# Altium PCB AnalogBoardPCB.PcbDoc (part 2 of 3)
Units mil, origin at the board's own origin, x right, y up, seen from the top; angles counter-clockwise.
Board outline 5875 x 2550 mil, 4 copper layers (Top Layer, GND, VCC, Bottom Layer); 569 components, 22 nets, 1336 pads, 360 vias.
Unrouted connection lines stored in the file: 31.
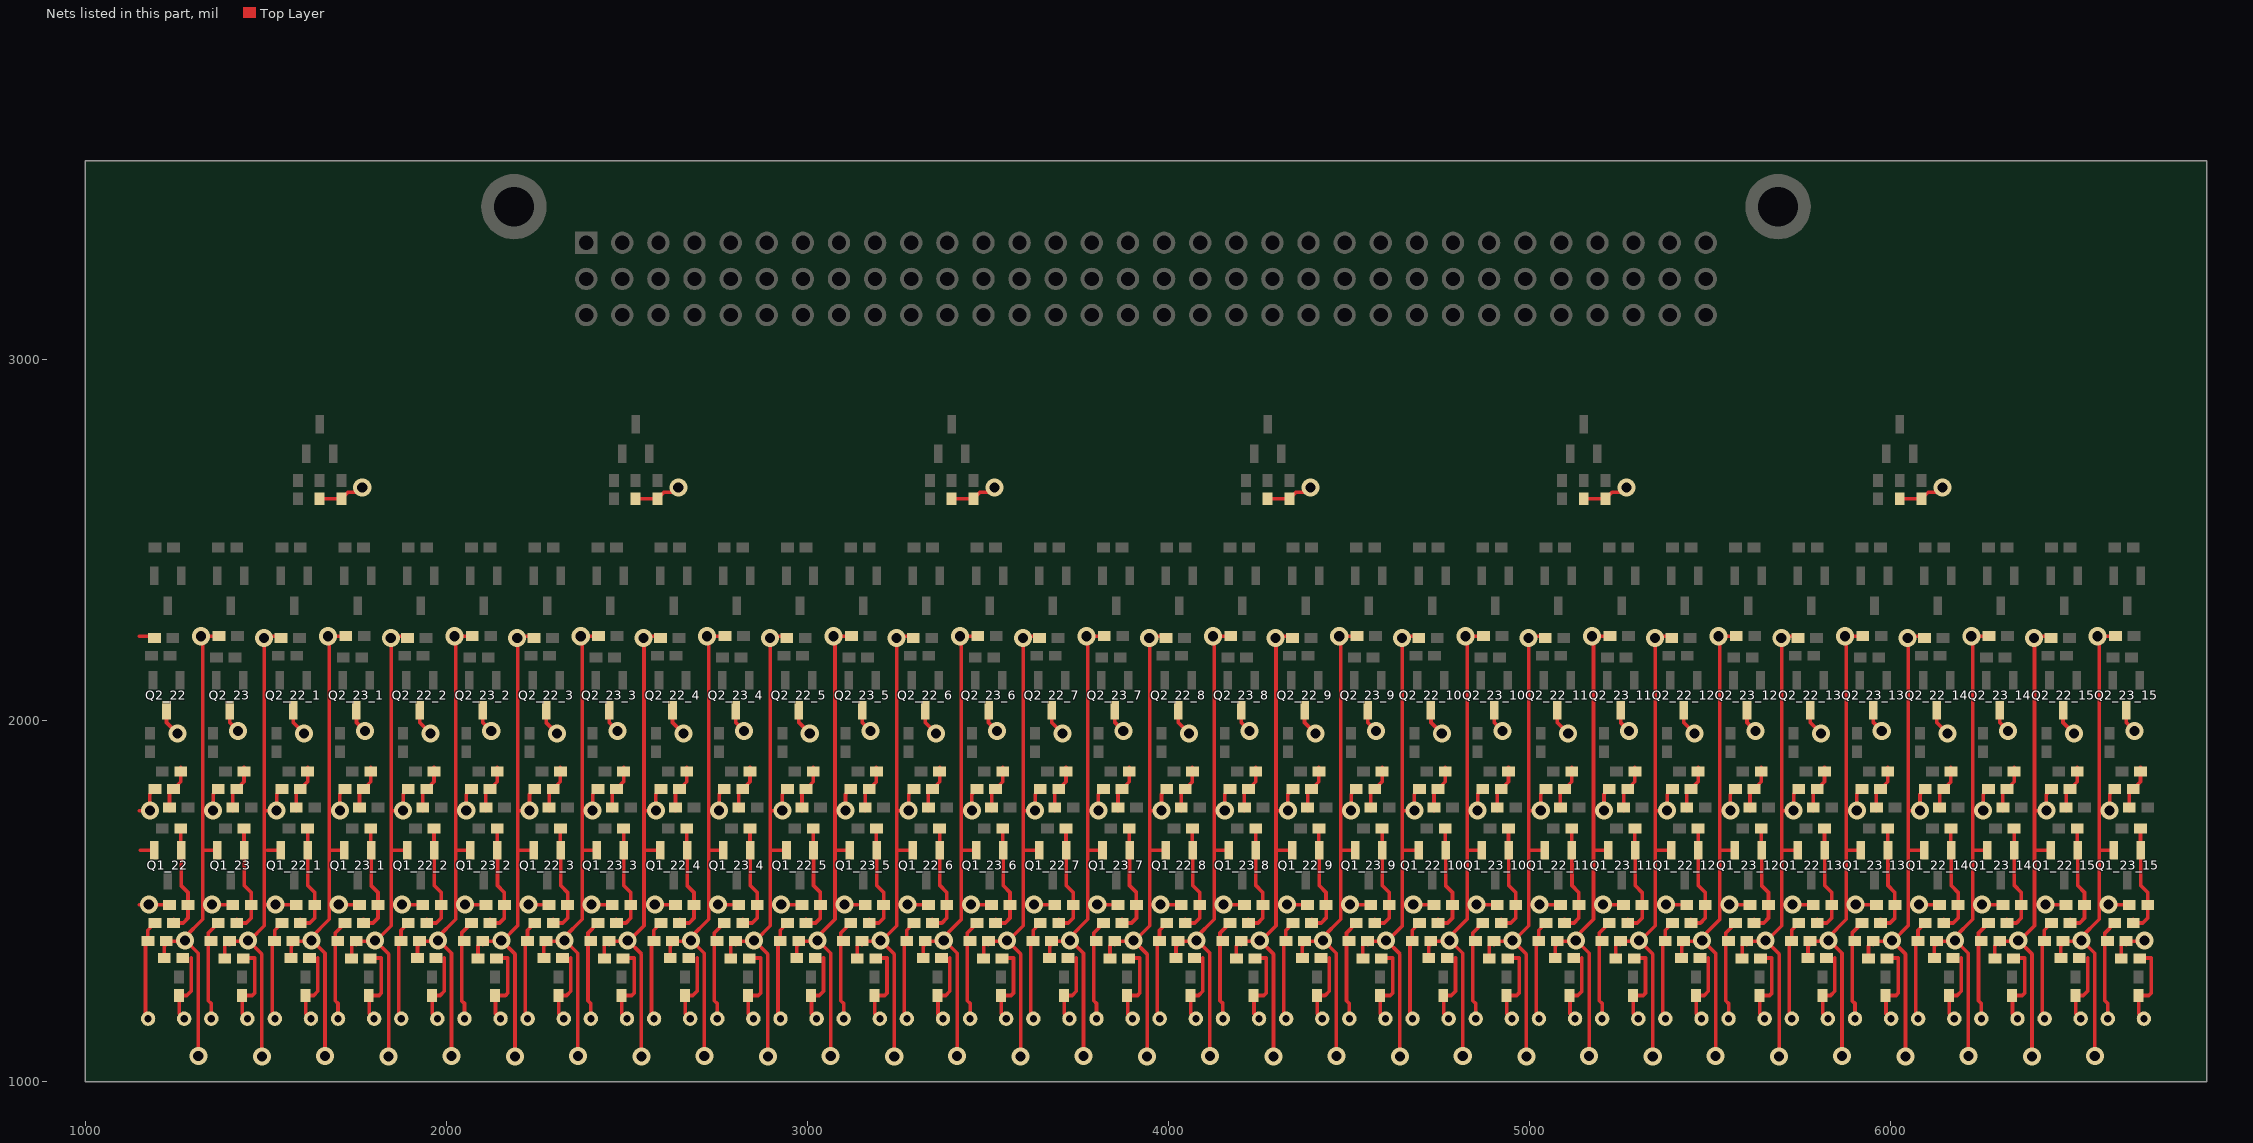
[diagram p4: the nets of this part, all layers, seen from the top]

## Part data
C1_22 C1_22_1 C1_22_2 C1_22_3 C1_22_4 C1_22_5 C1_22_6 C1_22_7 C1_22_8 C1_22_9 C1_22_10 C1_22_11 C1_22_12 C1_22_13 C1_22_14 C1_22_15 C1_23 C1_23_1 C1_23_2 C1_23_3 C1_23_4 C1_23_5 C1_23_6 C1_23_7 C1_23_8 C1_23_9 C1_23_10 C1_23_11 C1_23_12 C1_23_13 C1_23_14 C1_23_15 C2_22 C2_22_1 C2_22_2 C2_22_3 C2_22_4 C2_22_5 C2_22_6 C2_22_7 C2_22_8 C2_22_9 C2_22_10 C2_22_11 C2_22_12 C2_22_13 C2_22_14 C2_22_15 C2_23 C2_23_1 C2_23_2 C2_23_3 C2_23_4 C2_23_5 C2_23_6 C2_23_7 C2_23_8 C2_23_9 C2_23_10 C2_23_11 C2_23_12 C2_23_13 C2_23_14 C2_23_15 C3_22 C3_22_1 C3_22_2 C3_22_3 C3_22_4 C3_22_5 C3_22_6 C3_22_7 C3_22_8 C3_22_9 C3_22_10 C3_22_11 C3_22_12 C3_22_13 C3_22_14 C3_22_15 C3_23 C3_23_1 C3_23_2 C3_23_3 C3_23_4 C3_23_5 C3_23_6 C3_23_7 C3_23_8 C3_23_9 C3_23_10 C3_23_11 C3_23_12 C3_23_13 C3_23_14 C3_23_15 C4_22 C4_22_1 C4_22_2 C4_22_3 C4_22_4 C4_22_5 C4_22_6 C4_22_7 C4_22_8 C4_22_9 C4_22_10 C4_22_11 C4_22_12 C4_22_13 C4_22_14 C4_22_15 C4_23 C4_23_1 C4_23_2 C4_23_3 C4_23_4 C4_23_5 C4_23_6 C4_23_7 C4_23_8 C4_23_9 C4_23_10 C4_23_11 C4_23_12 C4_23_13 C4_23_14 C4_23_15: "Capacitor"
D1_22 D1_22_1 D1_22_2 D1_22_3 D1_22_4 D1_22_5 D1_22_6 D1_22_7 D1_22_8 D1_22_9 D1_22_10 D1_22_11 D1_22_12 D1_22_13 D1_22_14 D1_22_15 D1_23 D1_23_1 D1_23_2 D1_23_3 D1_23_4 D1_23_5 D1_23_6 D1_23_7 D1_23_8 D1_23_9 D1_23_10 D1_23_11 D1_23_12 D1_23_13 D1_23_14 D1_23_15: library part "Photo Sen", "Photosensitive Diode"
Q1_22 Q1_22_1 Q1_22_2 Q1_22_3 Q1_22_4 Q1_22_5 Q1_22_6 Q1_22_7 Q1_22_8 Q1_22_9 Q1_22_10 Q1_22_11 Q1_22_12 Q1_22_13 Q1_22_14 Q1_22_15 Q1_23 Q1_23_1 Q1_23_2 Q1_23_3 Q1_23_4 Q1_23_5 Q1_23_6 Q1_23_7 Q1_23_8 Q1_23_9 Q1_23_10 Q1_23_11 Q1_23_12 Q1_23_13 Q1_23_14 Q1_23_15 Q2_22 Q2_22_1 Q2_22_2 Q2_22_3 Q2_22_4 Q2_22_5 Q2_22_6 Q2_22_7 Q2_22_8 Q2_22_9 Q2_22_10 Q2_22_11 Q2_22_12 Q2_22_13 Q2_22_14 Q2_22_15 Q2_23 Q2_23_1 Q2_23_2 Q2_23_3 Q2_23_4 Q2_23_5 Q2_23_6 Q2_23_7 Q2_23_8 Q2_23_9 Q2_23_10 Q2_23_11 Q2_23_12 Q2_23_13 Q2_23_14 Q2_23_15: library part BFS19, "NPN Medium Frequency Transistor"
Q1_32 Q1_32_1 Q1_32_2 Q1_32_3 Q1_32_4 Q1_32_5: "NPN 3 GHz Wideband Transistor"
Q3_22 Q3_22_1 Q3_22_2 Q3_22_3 Q3_22_4 Q3_22_5 Q3_22_6 Q3_22_7 Q3_22_8 Q3_22_9 Q3_22_10 Q3_22_11 Q3_22_12 Q3_22_13 Q3_22_14 Q3_22_15 Q3_23 Q3_23_1 Q3_23_2 Q3_23_3 Q3_23_4 Q3_23_5 Q3_23_6 Q3_23_7 Q3_23_8 Q3_23_9 Q3_23_10 Q3_23_11 Q3_23_12 Q3_23_13 Q3_23_14 Q3_23_15: "PNP 5 GHz Wideband Transistor"
R1_22 R1_22_1 R1_22_2 R1_22_3 R1_22_4 R1_22_5 R1_22_6 R1_22_7 R1_22_8 R1_22_9 R1_22_10 R1_22_11 R1_22_12 R1_22_13 R1_22_14 R1_22_15 R1_23 R1_23_1 R1_23_2 R1_23_3 R1_23_4 R1_23_5 R1_23_6 R1_23_7 R1_23_8 R1_23_9 R1_23_10 R1_23_11 R1_23_12 R1_23_13 R1_23_14 R1_23_15 R1_32 R1_32_1 R1_32_2 R1_32_3 R1_32_4 R1_32_5 R2_22 R2_22_1 R2_22_2 R2_22_3 R2_22_4 R2_22_5 R2_22_6 R2_22_7 R2_22_8 R2_22_9 R2_22_10 R2_22_11 R2_22_12 R2_22_13 R2_22_14 R2_22_15 R2_23 R2_23_1 R2_23_2 R2_23_3 R2_23_4 R2_23_5 R2_23_6 R2_23_7 R2_23_8 R2_23_9 R2_23_10 R2_23_11 R2_23_12 R2_23_13 R2_23_14 R2_23_15 R2_32 R2_32_1 R2_32_2 R2_32_3 R2_32_4 R2_32_5 R3_22 R3_22_1 R3_22_2 R3_22_3 R3_22_4 R3_22_5 R3_22_6 R3_22_7 R3_22_8 R3_22_9 R3_22_10 R3_22_11 R3_22_12 R3_22_13 R3_22_14 R3_22_15 R3_23 R3_23_1 R3_23_2 R3_23_3 R3_23_4 R3_23_5 R3_23_6 R3_23_7 R3_23_8 R3_23_9 R3_23_10 R3_23_11 R3_23_12 R3_23_13 R3_23_14 R3_23_15 R3_32 R3_32_1 R3_32_2 R3_32_3 R3_32_4 R3_32_5 R4_22 R4_22_1 R4_22_2 R4_22_3 R4_22_4 R4_22_5 R4_22_6 R4_22_7 R4_22_8 R4_22_9 R4_22_10 R4_22_11 R4_22_12 R4_22_13 R4_22_14 R4_22_15 R4_23 R4_23_1 R4_23_2 R4_23_3 R4_23_4 R4_23_5 R4_23_6 R4_23_7 R4_23_8 R4_23_9 R4_23_10 R4_23_11 R4_23_12 R4_23_13 R4_23_14 R4_23_15 R5_22 R5_22_1 R5_22_2 R5_22_3 R5_22_4 R5_22_5 R5_22_6 R5_22_7 R5_22_8 R5_22_9 R5_22_10 R5_22_11 R5_22_12 R5_22_13 R5_22_14 R5_22_15 R5_23 R5_23_1 R5_23_2 R5_23_3 R5_23_4 R5_23_5 R5_23_6 R5_23_7 R5_23_8 R5_23_9 R5_23_10 R5_23_11 R5_23_12 R5_23_13 R5_23_14 R5_23_15 R6_22 R6_22_1 R6_22_2 R6_22_3 R6_22_4 R6_22_5 R6_22_6 R6_22_7 R6_22_8 R6_22_9 R6_22_10 R6_22_11 R6_22_12 R6_22_13 R6_22_14 R6_22_15 R6_23 R6_23_1 R6_23_2 R6_23_3 R6_23_4 R6_23_5 R6_23_6 R6_23_7 R6_23_8 R6_23_9 R6_23_10 R6_23_11 R6_23_12 R6_23_13 R6_23_14 R6_23_15 R7_22 R7_22_1 R7_22_2 R7_22_3 R7_22_4 R7_22_5 R7_22_6 R7_22_7 R7_22_8 R7_22_9 R7_22_10 R7_22_11 R7_22_12 R7_22_13 R7_22_14 R7_22_15 R7_23 R7_23_1 R7_23_2 R7_23_3 R7_23_4 R7_23_5 R7_23_6 R7_23_7 R7_23_8 R7_23_9 R7_23_10 R7_23_11 R7_23_12 R7_23_13 R7_23_14 R7_23_15 R8_22 R8_22_1 R8_22_2 R8_22_3 R8_22_4 R8_22_5 R8_22_6 R8_22_7 R8_22_8 R8_22_9 R8_22_10 R8_22_11 R8_22_12 R8_22_13 R8_22_14 R8_22_15 R8_23 R8_23_1 R8_23_2 R8_23_3 R8_23_4 R8_23_5 R8_23_6 R8_23_7 R8_23_8 R8_23_9 R8_23_10 R8_23_11 R8_23_12 R8_23_13 R8_23_14 R8_23_15 R9_22 R9_22_1 R9_22_2 R9_22_3 R9_22_4 R9_22_5 R9_22_6 R9_22_7 R9_22_8 R9_22_9 R9_22_10 R9_22_11 R9_22_12 R9_22_13 R9_22_14 R9_22_15 R9_23 R9_23_1 R9_23_2 R9_23_3 R9_23_4 R9_23_5 R9_23_6 R9_23_7 R9_23_8 R9_23_9 R9_23_10 R9_23_11 R9_23_12 R9_23_13 R9_23_14 R9_23_15: "Resistor"

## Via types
v1: diameter 50, hole 28, Top Layer to Bottom Layer, 327 vias
v2: diameter 50, hole 28, Top Layer to Bottom Layer, tented top, 31 vias
v3: diameter 50, hole 28, Top Layer to Bottom Layer, tented both sides, 2 vias

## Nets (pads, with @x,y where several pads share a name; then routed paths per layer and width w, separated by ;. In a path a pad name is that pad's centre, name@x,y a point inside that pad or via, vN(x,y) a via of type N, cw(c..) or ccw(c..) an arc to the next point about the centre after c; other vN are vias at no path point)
GND: C1_22.2 C1_22_1.2 C1_22_2.2 C1_22_3.2 C1_22_4.2 C1_22_5.2 C1_22_6.2 C1_22_7.2 C1_22_8.2 C1_22_9.2 C1_22_10.2 C1_22_11.2 C1_22_12.2 C1_22_13.2 C1_22_14.2 C1_22_15.2 C1_23.2 C1_23_1.2 C1_23_2.2 C1_23_3.2 C1_23_4.2 C1_23_5.2 C1_23_6.2 C1_23_7.2 C1_23_8.2 C1_23_9.2 C1_23_10.2 C1_23_11.2 C1_23_12.2 C1_23_13.2 C1_23_14.2 C1_23_15.2 C2_22.1 C2_22_1.1 C2_22_2.1 C2_22_3.1 C2_22_4.1 C2_22_5.1 C2_22_6.1 C2_22_7.1 C2_22_8.1 C2_22_9.1 C2_22_10.1 C2_22_11.1 C2_22_12.1 C2_22_13.1 C2_22_14.1 C2_22_15.1 C2_23.1 C2_23_1.1 C2_23_2.1 C2_23_3.1 C2_23_4.1 C2_23_5.1 C2_23_6.1 C2_23_7.1 C2_23_8.1 C2_23_9.1 C2_23_10.1 C2_23_11.1 C2_23_12.1 C2_23_13.1 C2_23_14.1 C2_23_15.1 Q1_22.2 Q1_22_1.2 Q1_22_2.2 Q1_22_3.2 Q1_22_4.2 Q1_22_5.2 Q1_22_6.2 Q1_22_7.2 Q1_22_8.2 Q1_22_9.2 Q1_22_10.2 Q1_22_11.2 Q1_22_12.2 Q1_22_13.2 Q1_22_14.2 Q1_22_15.2 Q1_23.2 Q1_23_1.2 Q1_23_2.2 Q1_23_3.2 Q1_23_4.2 Q1_23_5.2 Q1_23_6.2 Q1_23_7.2 Q1_23_8.2 Q1_23_9.2 Q1_23_10.2 Q1_23_11.2 Q1_23_12.2 Q1_23_13.2 Q1_23_14.2 Q1_23_15.2 Q2_22.3 Q2_22_1.3 Q2_22_2.3 Q2_22_3.3 Q2_22_4.3 Q2_22_5.3 Q2_22_6.3 Q2_22_7.3 Q2_22_8.3 Q2_22_9.3 Q2_22_10.3 Q2_22_11.3 Q2_22_12.3 Q2_22_13.3 Q2_22_14.3 Q2_22_15.3 Q2_23.3 Q2_23_1.3 Q2_23_2.3 Q2_23_3.3 Q2_23_4.3 Q2_23_5.3 Q2_23_6.3 Q2_23_7.3 Q2_23_8.3 Q2_23_9.3 Q2_23_10.3 Q2_23_11.3 Q2_23_12.3 Q2_23_13.3 Q2_23_14.3 Q2_23_15.3 R2_32.1 R2_32_1.1 R2_32_2.1 R2_32_3.1 R2_32_4.1 R2_32_5.1 R3_32.1 R3_32_1.1 R3_32_2.1 R3_32_3.1 R3_32_4.1 R3_32_5.1 R6_22.1 R6_22_1.1 R6_22_2.1 R6_22_3.1 R6_22_4.1 R6_22_5.1 R6_22_6.1 R6_22_7.1 R6_22_8.1 R6_22_9.1 R6_22_10.1 R6_22_11.1 R6_22_12.1 R6_22_13.1 R6_22_14.1 R6_22_15.1 R6_23.1 R6_23_1.1 R6_23_2.1 R6_23_3.1 R6_23_4.1 R6_23_5.1 R6_23_6.1 R6_23_7.1 R6_23_8.1 R6_23_9.1 R6_23_10.1 R6_23_11.1 R6_23_12.1 R6_23_13.1 R6_23_14.1 R6_23_15.1 R7_22.1 R7_22_1.1 R7_22_2.1 R7_22_3.1 R7_22_4.1 R7_22_5.1 R7_22_6.1 R7_22_7.1 R7_22_8.1 R7_22_9.1 R7_22_10.1 R7_22_11.1 R7_22_12.1 R7_22_13.1 R7_22_14.1 R7_22_15.1 R7_23.1 R7_23_1.1 R7_23_2.1 R7_23_3.1 R7_23_4.1 R7_23_5.1 R7_23_6.1 R7_23_7.1 R7_23_8.1 R7_23_9.1 R7_23_10.1 R7_23_11.1 R7_23_12.1 R7_23_13.1 R7_23_14.1 R7_23_15.1 R8_22.1 R8_22_1.1 R8_22_2.1 R8_22_3.1 R8_22_4.1 R8_22_5.1 R8_22_6.1 R8_22_7.1 R8_22_8.1 R8_22_9.1 R8_22_10.1 R8_22_11.1 R8_22_12.1 R8_22_13.1 R8_22_14.1 R8_22_15.1 R8_23.1 R8_23_1.1 R8_23_2.1 R8_23_3.1 R8_23_4.1 R8_23_5.1 R8_23_6.1 R8_23_7.1 R8_23_8.1 R8_23_9.1 R8_23_10.1 R8_23_11.1 R8_23_12.1 R8_23_13.1 R8_23_14.1 R8_23_15.1 | length 51418.7
  Top Layer w10: 1150.5,1490 1213.91,1490 ; 1150.5,1750 v1(1179.5,1750) 1179.5,1795.59 C2_22.1@1193.91,1810 ; 1150.5,2233 R7_22.1@1178.91,2233 ; 1153.16,1640.34 Q1_22.2@1191.1,1640.34 ; C1_22.2@1219.5,1342 1219.5,1383.41 R6_22.1@1225.09,1389 ; R6_22.1@1225.09,1379.59 R6_22.1@1225.09,1389 ; Q2_22.3@1225.5,2028.66 1225.5,1994 v1(1255.5,1964) ; v1@1274.5,1389 R6_22.1@1225.09,1389 ; v2(1313.5,1071) 1313.5,1355 1276.5,1392 1276.5,1400 1325.5,1449 1325.5,2233 R7_23.1@1374.91,2233 ; 1325.5,1490 1388.91,1490 ; 1325.5,1750 v1(1354.5,1750) 1354.5,1795.59 C2_23.1@1368.91,1810 ; 1328.16,1640.34 Q1_23.2@1366.1,1640.34 ; C1_23.2@1386.91,1341 1386.91,1375.82 R6_23.1@1400.09,1389 ; R6_23.1@1400.09,1379.59 R6_23.1@1400.09,1389 ; Q2_23.3@1400.5,2028.66 1400.5,1994 v1@1430.5,1964 ; v1@1449.5,1389 R6_23.1@1400.09,1389 ; v2(1489.5,1069) 1489.5,1353 v1(1451.5,1391) 1456.5,1391 1496.5,1431 v1@1496.5,2228 ; 1501.5,1490 1564.91,1490 ; 1501.5,1750 v1(1530.5,1750) 1530.5,1795.59 C2_22_1.1@1544.91,1810 ; v1@1501.5,2233 R7_22_1.1@1529.91,2233 ; 1504.16,1640.34 Q1_22_1.2@1542.1,1640.34 ; C1_22_1.2@1570.5,1342 1570.5,1383.41 R6_22_1.1@1576.09,1389 ; R6_22_1.1@1576.09,1379.59 R6_22_1.1@1576.09,1389 ; Q2_22_1.3@1576.5,2028.66 1576.5,1994 v1(1606.5,1964) ; v1@1625.5,1389 R6_22_1.1@1576.09,1389 ; R2_32.1@1649.5,2613.41 R3_32.1@1709.5,2613.41 1727.96,2631.87 1754.37,2631.87 v1(1767.5,2645) ; v2(1664.5,1071) 1664.5,1355 1627.5,1392 1627.5,1400 1676.5,1449 1676.5,2233 R7_23_1.1@1725.91,2233 ; 1676.5,1490 1739.91,1490 ; 1676.5,1750 v1(1705.5,1750) 1705.5,1795.59 C2_23_1.1@1719.91,1810 ; 1679.16,1640.34 Q1_23_1.2@1717.1,1640.34 ; C1_23_1.2@1737.91,1341 1737.91,1375.82 R6_23_1.1@1751.09,1389 ; R6_23_1.1@1751.09,1379.59 R6_23_1.1@1751.09,1389 ; Q2_23_1.3@1751.5,2028.66 1751.5,1994 v1@1781.5,1964 ; v1@1800.5,1389 R6_23_1.1@1751.09,1389 ; v2(1840.5,1069) 1840.5,1353 v1(1802.5,1391) 1807.5,1391 1847.5,1431 v1@1847.5,2228 ; 1851.5,1490 1914.91,1490 ; 1851.5,1750 v1(1880.5,1750) 1880.5,1795.59 C2_22_2.1@1894.91,1810 ; v1@1851.5,2233 R7_22_2.1@1879.91,2233 ; 1854.16,1640.34 Q1_22_2.2@1892.1,1640.34 ; C1_22_2.2@1920.5,1342 1920.5,1383.41 R6_22_2.1@1926.09,1389 ; R6_22_2.1@1926.09,1379.59 R6_22_2.1@1926.09,1389 ; Q2_22_2.3@1926.5,2028.66 1926.5,1994 v1(1956.5,1964) ; v1@1975.5,1389 R6_22_2.1@1926.09,1389 ; v2(2014.5,1071) 2014.5,1355 1977.5,1392 1977.5,1400 2026.5,1449 2026.5,2233 R7_23_2.1@2075.91,2233 ; 2026.5,1490 2089.91,1490 ; 2026.5,1750 v1(2055.5,1750) 2055.5,1795.59 C2_23_2.1@2069.91,1810 ; 2029.16,1640.34 Q1_23_2.2@2067.1,1640.34 ; C1_23_2.2@2087.91,1341 2087.91,1375.82 R6_23_2.1@2101.09,1389 ; R6_23_2.1@2101.09,1379.59 R6_23_2.1@2101.09,1389 ; Q2_23_2.3@2101.5,2028.66 2101.5,1994 v1@2131.5,1964 ; v1@2150.5,1389 R6_23_2.1@2101.09,1389 ; v2(2190.5,1069) 2190.5,1353 v1(2152.5,1391) 2157.5,1391 2197.5,1431 v1@2197.5,2228 ; 2201.5,1490 2264.91,1490 ; 2201.5,1750 v1(2230.5,1750) 2230.5,1795.59 C2_22_3.1@2244.91,1810 ; v1@2201.5,2233 R7_22_3.1@2229.91,2233 ; 2204.16,1640.34 Q1_22_3.2@2242.1,1640.34 ; C1_22_3.2@2270.5,1342 2270.5,1383.41 R6_22_3.1@2276.09,1389 ; R6_22_3.1@2276.09,1379.59 R6_22_3.1@2276.09,1389 ; Q2_22_3.3@2276.5,2028.66 2276.5,1994 v1(2306.5,1964) ; v1@2325.5,1389 R6_22_3.1@2276.09,1389 ; v2(2364.5,1071) 2364.5,1355 2327.5,1392 2327.5,1400 2376.5,1449 2376.5,2233 R7_23_3.1@2425.91,2233 ; 2376.5,1490 2439.91,1490 ; 2376.5,1750 v1(2405.5,1750) 2405.5,1795.59 C2_23_3.1@2419.91,1810 ; 2379.16,1640.34 Q1_23_3.2@2417.1,1640.34 ; C1_23_3.2@2437.91,1341 2437.91,1375.82 R6_23_3.1@2451.09,1389 ; R6_23_3.1@2451.09,1379.59 R6_23_3.1@2451.09,1389 ; Q2_23_3.3@2451.5,2028.66 2451.5,1994 v1@2481.5,1964 ; v1@2500.5,1389 R6_23_3.1@2451.09,1389 ; R2_32_1.1@2524.5,2613.41 R3_32_1.1@2584.5,2613.41 2602.96,2631.87 2629.37,2631.87 v1(2642.5,2645) ; v2(2540.5,1069) 2540.5,1353 v1(2502.5,1391) 2507.5,1391 2547.5,1431 v1@2547.5,2228 ; 2551.5,1490 2614.91,1490 ; 2551.5,1750 v1(2580.5,1750) 2580.5,1795.59 C2_22_4.1@2594.91,1810 ; v1@2551.5,2233 R7_22_4.1@2579.91,2233 ; 2554.16,1640.34 Q1_22_4.2@2592.1,1640.34 ; C1_22_4.2@2620.5,1342 2620.5,1383.41 R6_22_4.1@2626.09,1389 ; R6_22_4.1@2626.09,1379.59 R6_22_4.1@2626.09,1389 ; Q2_22_4.3@2626.5,2028.66 2626.5,1994 v1(2656.5,1964) ; v1@2675.5,1389 R6_22_4.1@2626.09,1389 ; v2(2714.5,1071) 2714.5,1355 2677.5,1392 2677.5,1400 2726.5,1449 2726.5,2233 R7_23_4.1@2775.91,2233 ; 2726.5,1490 2789.91,1490 ; 2726.5,1750 v1(2755.5,1750) 2755.5,1795.59 C2_23_4.1@2769.91,1810 ; 2729.16,1640.34 Q1_23_4.2@2767.1,1640.34 ; C1_23_4.2@2787.91,1341 2787.91,1375.82 R6_23_4.1@2801.09,1389 ; R6_23_4.1@2801.09,1379.59 R6_23_4.1@2801.09,1389 ; Q2_23_4.3@2801.5,2028.66 2801.5,1994 v1@2831.5,1964 ; v1@2850.5,1389 R6_23_4.1@2801.09,1389 ; v2(2890.5,1069) 2890.5,1353 v1(2852.5,1391) 2857.5,1391 2897.5,1431 v1@2897.5,2228 ; 2901.5,1490 2964.91,1490 ; 2901.5,1750 v1(2930.5,1750) 2930.5,1795.59 C2_22_5.1@2944.91,1810 ; v1@2901.5,2233 R7_22_5.1@2929.91,2233 ; 2904.16,1640.34 Q1_22_5.2@2942.1,1640.34 ; C1_22_5.2@2970.5,1342 2970.5,1383.41 R6_22_5.1@2976.09,1389 ; R6_22_5.1@2976.09,1379.59 R6_22_5.1@2976.09,1389 ; Q2_22_5.3@2976.5,2028.66 2976.5,1994 v1(3006.5,1964) ; v1@3025.5,1389 R6_22_5.1@2976.09,1389 ; v2(3064.5,1071) 3064.5,1355 3027.5,1392 3027.5,1400 3076.5,1449 3076.5,2233 R7_23_5.1@3125.91,2233 ; 3076.5,1490 3139.91,1490 ; 3076.5,1750 v1(3105.5,1750) 3105.5,1795.59 C2_23_5.1@3119.91,1810 ; 3079.16,1640.34 Q1_23_5.2@3117.1,1640.34 ; C1_23_5.2@3137.91,1341 3137.91,1375.82 R6_23_5.1@3151.09,1389 ; R6_23_5.1@3151.09,1379.59 R6_23_5.1@3151.09,1389 ; Q2_23_5.3@3151.5,2028.66 3151.5,1994 v1@3181.5,1964 ; v1@3200.5,1389 R6_23_5.1@3151.09,1389 ; v2(3240.5,1069) 3240.5,1353 v1(3202.5,1391) 3207.5,1391 3247.5,1431 v1@3247.5,2228 ; 3251.5,1490 3314.91,1490 ; 3251.5,1750 v1(3280.5,1750) 3280.5,1795.59 C2_22_6.1@3294.91,1810 ; v1@3251.5,2233 R7_22_6.1@3279.91,2233 ; 3254.16,1640.34 Q1_22_6.2@3292.1,1640.34 ; C1_22_6.2@3320.5,1342 3320.5,1383.41 R6_22_6.1@3326.09,1389 ; R6_22_6.1@3326.09,1379.59 R6_22_6.1@3326.09,1389 ; Q2_22_6.3@3326.5,2028.66 3326.5,1994 v1(3356.5,1964) ; v1@3375.5,1389 R6_22_6.1@3326.09,1389 ; R2_32_2.1@3399.5,2613.41 R3_32_2.1@3459.5,2613.41 3477.96,2631.87 3504.37,2631.87 v1(3517.5,2645) ; v2(3414.5,1071) 3414.5,1355 3377.5,1392 3377.5,1400 3426.5,1449 3426.5,2233 R7_23_6.1@3475.91,2233 ; 3426.5,1490 3489.91,1490 ; 3426.5,1750 v1(3455.5,1750) 3455.5,1795.59 C2_23_6.1@3469.91,1810 ; 3429.16,1640.34 Q1_23_6.2@3467.1,1640.34 ; C1_23_6.2@3487.91,1341 3487.91,1375.82 R6_23_6.1@3501.09,1389 ; R6_23_6.1@3501.09,1379.59 R6_23_6.1@3501.09,1389 ; Q2_23_6.3@3501.5,2028.66 3501.5,1994 v1@3531.5,1964 ; v1@3550.5,1389 R6_23_6.1@3501.09,1389 ; v2(3590.5,1069) 3590.5,1353 v1(3552.5,1391) 3557.5,1391 3597.5,1431 v1@3597.5,2228 ; 3601.5,1490 3664.91,1490 ; 3601.5,1750 v1(3630.5,1750) 3630.5,1795.59 C2_22_7.1@3644.91,1810 ; v1@3601.5,2233 R7_22_7.1@3629.91,2233 ; 3604.16,1640.34 Q1_22_7.2@3642.1,1640.34 ; C1_22_7.2@3670.5,1342 3670.5,1383.41 R6_22_7.1@3676.09,1389 ; R6_22_7.1@3676.09,1379.59 R6_22_7.1@3676.09,1389 ; Q2_22_7.3@3676.5,2028.66 3676.5,1994 v1(3706.5,1964) ; v1@3725.5,1389 R6_22_7.1@3676.09,1389 ; v2(3764.5,1071) 3764.5,1355 3727.5,1392 3727.5,1400 3776.5,1449 3776.5,2233 R7_23_7.1@3825.91,2233 ; 3776.5,1490 3839.91,1490 ; 3776.5,1750 v1(3805.5,1750) 3805.5,1795.59 C2_23_7.1@3819.91,1810 ; 3779.16,1640.34 Q1_23_7.2@3817.1,1640.34 ; C1_23_7.2@3837.91,1341 3837.91,1375.82 R6_23_7.1@3851.09,1389 ; R6_23_7.1@3851.09,1379.59 R6_23_7.1@3851.09,1389 ; Q2_23_7.3@3851.5,2028.66 3851.5,1994 v1@3881.5,1964 ; v1@3900.5,1389 R6_23_7.1@3851.09,1389 ; v2(3940.5,1069) 3940.5,1353 v1(3902.5,1391) 3907.5,1391 3947.5,1431 v1@3947.5,2228 ; 3951.5,1490 4014.91,1490 ; 3951.5,1750 v1(3980.5,1750) 3980.5,1795.59 C2_22_8.1@3994.91,1810 ; v1@3951.5,2233 R7_22_8.1@3979.91,2233 ; 3954.16,1640.34 Q1_22_8.2@3992.1,1640.34 ; C1_22_8.2@4020.5,1342 4020.5,1383.41 R6_22_8.1@4026.09,1389 ; R6_22_8.1@4026.09,1379.59 R6_22_8.1@4026.09,1389 ; Q2_22_8.3@4026.5,2028.66 4026.5,1994 v1(4056.5,1964) ; v1@4075.5,1389 R6_22_8.1@4026.09,1389 ; v2(4114.5,1071) 4114.5,1355 4077.5,1392 4077.5,1400 4126.5,1449 4126.5,2233 R7_23_8.1@4175.91,2233 ; 4126.5,1490 4189.91,1490 ; 4126.5,1750 v1(4155.5,1750) 4155.5,1795.59 C2_23_8.1@4169.91,1810 ; 4129.16,1640.34 Q1_23_8.2@4167.1,1640.34 ; C1_23_8.2@4187.91,1341 4187.91,1375.82 R6_23_8.1@4201.09,1389 ; R6_23_8.1@4201.09,1379.59 R6_23_8.1@4201.09,1389 ; Q2_23_8.3@4201.5,2028.66 4201.5,1994 v1@4231.5,1964 ; v1@4250.5,1389 R6_23_8.1@4201.09,1389 ; R2_32_3.1@4274.5,2613.41 R3_32_3.1@4334.5,2613.41 4352.96,2631.87 4379.37,2631.87 v1(4392.5,2645) ; v2(4290.5,1069) 4290.5,1353 v1(4252.5,1391) 4257.5,1391 4297.5,1431 v1@4297.5,2228 ; 4301.5,1490 4364.91,1490 ; 4301.5,1750 v1(4330.5,1750) 4330.5,1795.59 C2_22_9.1@4344.91,1810 ; v1@4301.5,2233 R7_22_9.1@4329.91,2233 ; 4304.16,1640.34 Q1_22_9.2@4342.1,1640.34 ; C1_22_9.2@4370.5,1342 4370.5,1383.41 R6_22_9.1@4376.09,1389 ; R6_22_9.1@4376.09,1379.59 R6_22_9.1@4376.09,1389 ; Q2_22_9.3@4376.5,2028.66 4376.5,1994 v1(4406.5,1964) ; v1@4425.5,1389 R6_22_9.1@4376.09,1389 ; v2(4464.5,1071) 4464.5,1355 4427.5,1392 4427.5,1400 4476.5,1449 4476.5,2233 R7_23_9.1@4525.91,2233 ; 4476.5,1490 4539.91,1490 ; 4476.5,1750 v1(4505.5,1750) 4505.5,1795.59 C2_23_9.1@4519.91,1810 ; 4479.16,1640.34 Q1_23_9.2@4517.1,1640.34 ; C1_23_9.2@4537.91,1341 4537.91,1375.82 R6_23_9.1@4551.09,1389 ; R6_23_9.1@4551.09,1379.59 R6_23_9.1@4551.09,1389 ; Q2_23_9.3@4551.5,2028.66 4551.5,1994 v1@4581.5,1964 ; v1@4600.5,1389 R6_23_9.1@4551.09,1389 ; v2(4640.5,1069) 4640.5,1353 v1(4602.5,1391) 4607.5,1391 4647.5,1431 v1@4647.5,2228 ; 4651.5,1490 4714.91,1490 ; 4651.5,1750 v1(4680.5,1750) 4680.5,1795.59 C2_22_10.1@4694.91,1810 ; v1@4651.5,2233 R7_22_10.1@4679.91,2233 ; 4654.16,1640.34 Q1_22_10.2@4692.1,1640.34 ; C1_22_10.2@4720.5,1342 4720.5,1383.41 R6_22_10.1@4726.09,1389 ; R6_22_10.1@4726.09,1379.59 R6_22_10.1@4726.09,1389 ; Q2_22_10.3@4726.5,2028.66 4726.5,1994 v1(4756.5,1964) ; v1@4775.5,1389 R6_22_10.1@4726.09,1389 ; v2(4814.5,1071) 4814.5,1355 4777.5,1392 4777.5,1400 4826.5,1449 4826.5,2233 R7_23_10.1@4875.91,2233 ; 4826.5,1490 4889.91,1490 ; 4826.5,1750 v1(4855.5,1750) 4855.5,1795.59 C2_23_10.1@4869.91,1810 ; 4829.16,1640.34 Q1_23_10.2@4867.1,1640.34 ; C1_23_10.2@4887.91,1341 4887.91,1375.82 R6_23_10.1@4901.09,1389 ; R6_23_10.1@4901.09,1379.59 R6_23_10.1@4901.09,1389 ; Q2_23_10.3@4901.5,2028.66 4901.5,1994 v1@4931.5,1964 ; v1@4950.5,1389 R6_23_10.1@4901.09,1389 ; v2(4990.5,1069) 4990.5,1353 v1(4952.5,1391) 4957.5,1391 4997.5,1431 v1@4997.5,2228 ; 5001.5,1490 5064.91,1490 ; 5001.5,1750 v1(5030.5,1750) 5030.5,1795.59 C2_22_11.1@5044.91,1810 ; v1@5001.5,2233 R7_22_11.1@5029.91,2233 ; 5004.16,1640.34 Q1_22_11.2@5042.1,1640.34 ; C1_22_11.2@5070.5,1342 5070.5,1383.41 R6_22_11.1@5076.09,1389 ; R6_22_11.1@5076.09,1379.59 R6_22_11.1@5076.09,1389 ; Q2_22_11.3@5076.5,2028.66 5076.5,1994 v1(5106.5,1964) ; v1@5125.5,1389 R6_22_11.1@5076.09,1389 ; R2_32_4.1@5149.5,2613.41 R3_32_4.1@5209.5,2613.41 5227.96,2631.87 5254.37,2631.87 v1(5267.5,2645) ; v2(5164.5,1071) 5164.5,1355 5127.5,1392 5127.5,1400 5176.5,1449 5176.5,2233 R7_23_11.1@5225.91,2233 ; 5176.5,1490 5239.91,1490 ; 5176.5,1750 v1(5205.5,1750) 5205.5,1795.59 C2_23_11.1@5219.91,1810 ; 5179.16,1640.34 Q1_23_11.2@5217.1,1640.34 ; C1_23_11.2@5237.91,1341 5237.91,1375.82 R6_23_11.1@5251.09,1389 ; R6_23_11.1@5251.09,1379.59 R6_23_11.1@5251.09,1389 ; Q2_23_11.3@5251.5,2028.66 5251.5,1994 v1@5281.5,1964 ; v1@5300.5,1389 R6_23_11.1@5251.09,1389 ; v2(5340.5,1069) 5340.5,1353 v1(5302.5,1391) 5307.5,1391 5347.5,1431 v1@5347.5,2228 ; 5351.5,1490 5414.91,1490 ; 5351.5,1750 v1(5380.5,1750) 5380.5,1795.59 C2_22_12.1@5394.91,1810 ; v1@5351.5,2233 R7_22_12.1@5379.91,2233 ; 5354.16,1640.34 Q1_22_12.2@5392.1,1640.34 ; C1_22_12.2@5420.5,1342 5420.5,1383.41 R6_22_12.1@5426.09,1389 ; R6_22_12.1@5426.09,1379.59 R6_22_12.1@5426.09,1389 ; Q2_22_12.3@5426.5,2028.66 5426.5,1994 v1(5456.5,1964) ; v1@5475.5,1389 R6_22_12.1@5426.09,1389 ; v2(5514.5,1071) 5514.5,1355 5477.5,1392 5477.5,1400 5526.5,1449 5526.5,2233 R7_23_12.1@5575.91,2233 ; 5526.5,1490 5589.91,1490 ; 5526.5,1750 v1(5555.5,1750) 5555.5,1795.59 C2_23_12.1@5569.91,1810 ; 5529.16,1640.34 Q1_23_12.2@5567.1,1640.34 ; C1_23_12.2@5587.91,1341 5587.91,1375.82 R6_23_12.1@5601.09,1389 ; R6_23_12.1@5601.09,1379.59 R6_23_12.1@5601.09,1389 ; Q2_23_12.3@5601.5,2028.66 5601.5,1994 v1@5631.5,1964 ; v1@5650.5,1389 R6_23_12.1@5601.09,1389 ; v2(5690.5,1069) 5690.5,1353 v1(5652.5,1391) 5657.5,1391 5697.5,1431 v1@5697.5,2228 ; 5701.5,1490 5764.91,1490 ; 5701.5,1750 v1(5730.5,1750) 5730.5,1795.59 C2_22_13.1@5744.91,1810 ; v1@5701.5,2233 R7_22_13.1@5729.91,2233 ; 5704.16,1640.34 Q1_22_13.2@5742.1,1640.34 ; C1_22_13.2@5770.5,1342 5770.5,1383.41 R6_22_13.1@5776.09,1389 ; R6_22_13.1@5776.09,1379.59 R6_22_13.1@5776.09,1389 ; Q2_22_13.3@5776.5,2028.66 5776.5,1994 v1(5806.5,1964) ; v1@5825.5,1389 R6_22_13.1@5776.09,1389 ; v2(5864.5,1071) 5864.5,1355 5827.5,1392 5827.5,1400 5876.5,1449 5876.5,2233 R7_23_13.1@5925.91,2233 ; 5876.5,1490 5939.91,1490 ; 5876.5,1750 v1(5905.5,1750) 5905.5,1795.59 C2_23_13.1@5919.91,1810 ; 5879.16,1640.34 Q1_23_13.2@5917.1,1640.34 ; C1_23_13.2@5937.91,1341 5937.91,1375.82 R6_23_13.1@5951.09,1389 ; R6_23_13.1@5951.09,1379.59 R6_23_13.1@5951.09,1389 ; Q2_23_13.3@5951.5,2028.66 5951.5,1994 v1@5981.5,1964 ; v1@6000.5,1389 R6_23_13.1@5951.09,1389 ; R2_32_5.1@6024.5,2613.41 R3_32_5.1@6084.5,2613.41 6102.96,2631.87 6129.37,2631.87 v1(6142.5,2645) ; v2(6040.5,1069) 6040.5,1353 v1(6002.5,1391) 6007.5,1391 6047.5,1431 v1@6047.5,2228 ; 6051.5,1490 6114.91,1490 ; 6051.5,1750 v1(6080.5,1750) 6080.5,1795.59 C2_22_14.1@6094.91,1810 ; v1@6051.5,2233 R7_22_14.1@6079.91,2233 ; 6054.16,1640.34 Q1_22_14.2@6092.1,1640.34 ; C1_22_14.2@6120.5,1342 6120.5,1383.41 R6_22_14.1@6126.09,1389 ; R6_22_14.1@6126.09,1379.59 R6_22_14.1@6126.09,1389 ; Q2_22_14.3@6126.5,2028.66 6126.5,1994 v1(6156.5,1964) ; v1@6175.5,1389 R6_22_14.1@6126.09,1389 ; v2(6214.5,1071) 6214.5,1355 6177.5,1392 6177.5,1400 6226.5,1449 6226.5,2233 R7_23_14.1@6275.91,2233 ; 6226.5,1490 6289.91,1490 ; 6226.5,1750 v1(6255.5,1750) 6255.5,1795.59 C2_23_14.1@6269.91,1810 ; 6229.16,1640.34 Q1_23_14.2@6267.1,1640.34 ; C1_23_14.2@6287.91,1341 6287.91,1375.82 R6_23_14.1@6301.09,1389 ; R6_23_14.1@6301.09,1379.59 R6_23_14.1@6301.09,1389 ; Q2_23_14.3@6301.5,2028.66 6301.5,1994 v1@6331.5,1964 ; v1@6350.5,1389 R6_23_14.1@6301.09,1389 ; v2(6390.5,1069) 6390.5,1353 v1(6352.5,1391) 6357.5,1391 6397.5,1431 v1@6397.5,2228 ; 6401.5,1490 6464.91,1490 ; 6401.5,1750 v1(6430.5,1750) 6430.5,1795.59 C2_22_15.1@6444.91,1810 ; v1@6401.5,2233 R7_22_15.1@6429.91,2233 ; 6404.16,1640.34 Q1_22_15.2@6442.1,1640.34 ; C1_22_15.2@6470.5,1342 6470.5,1383.41 R6_22_15.1@6476.09,1389 ; R6_22_15.1@6476.09,1379.59 R6_22_15.1@6476.09,1389 ; Q2_22_15.3@6476.5,2028.66 6476.5,1994 v1(6506.5,1964) ; v1@6525.5,1389 R6_22_15.1@6476.09,1389 ; v2(6564.5,1071) 6564.5,1355 6527.5,1392 6527.5,1400 6576.5,1449 6576.5,2233 R7_23_15.1@6625.91,2233 ; 6576.5,1490 6639.91,1490 ; 6576.5,1750 v1(6605.5,1750) 6605.5,1795.59 C2_23_15.1@6619.91,1810 ; 6579.16,1640.34 Q1_23_15.2@6617.1,1640.34 ; C1_23_15.2@6637.91,1341 6637.91,1375.82 R6_23_15.1@6651.09,1389 ; R6_23_15.1@6651.09,1379.59 R6_23_15.1@6651.09,1389 ; Q2_23_15.3@6651.5,2028.66 6651.5,1994 v1@6681.5,1964 ; v1@6700.5,1389 R6_23_15.1@6651.09,1389 ; v1(6702.5,1391) v1@6707.5,1391
  other v1: 1276.5,1391 1627.5,1391 1977.5,1391 2327.5,1391 2677.5,1391 3027.5,1391 3377.5,1391 3727.5,1391 4077.5,1391 4427.5,1391 4777.5,1391 5127.5,1391 5477.5,1391 5827.5,1391 6177.5,1391 6527.5,1391 1176.5,1490 1351.5,1490 1527.5,1490 1702.5,1490 1877.5,1490 2052.5,1490 2227.5,1490 2402.5,1490 2577.5,1490 2752.5,1490 2927.5,1490 3102.5,1490 3277.5,1490 3452.5,1490 3627.5,1490 3802.5,1490 3977.5,1490 4152.5,1490 4327.5,1490 4502.5,1490 4677.5,1490 4852.5,1490 5027.5,1490 5202.5,1490 5377.5,1490 5552.5,1490 5727.5,1490 5902.5,1490 6077.5,1490 6252.5,1490 6427.5,1490 6602.5,1490 1423.6,1970.9 1774.6,1970.9 2124.6,1970.9 2474.6,1970.9 2824.6,1970.9 3174.6,1970.9 3524.6,1970.9 3874.6,1970.9 4224.6,1970.9 4574.6,1970.9 4924.6,1970.9 5274.6,1970.9 5624.6,1970.9 5974.6,1970.9 6324.6,1970.9 6674.6,1970.9 1495.5,2228 1846.5,2228 2196.5,2228 2546.5,2228 2896.5,2228 3246.5,2228 3596.5,2228 3946.5,2228 4296.5,2228 4646.5,2228 4996.5,2228 5346.5,2228 5696.5,2228 6046.5,2228 6396.5,2228 1321.5,2233 1672.5,2233 2022.5,2233 2372.5,2233 2722.5,2233 3072.5,2233 3422.5,2233 3772.5,2233 4122.5,2233 4472.5,2233 4822.5,2233 5172.5,2233 5522.5,2233 5872.5,2233 6222.5,2233 6572.5,2233
NetC1_1: C1_22.1 C1_22_1.1 C1_22_2.1 C1_22_3.1 C1_22_4.1 C1_22_5.1 C1_22_6.1 C1_22_7.1 C1_22_8.1 C1_22_9.1 C1_22_10.1 C1_22_11.1 C1_22_12.1 C1_22_13.1 C1_22_14.1 C1_22_15.1 C1_23.1 C1_23_1.1 C1_23_2.1 C1_23_3.1 C1_23_4.1 C1_23_5.1 C1_23_6.1 C1_23_7.1 C1_23_8.1 C1_23_9.1 C1_23_10.1 C1_23_11.1 C1_23_12.1 C1_23_13.1 C1_23_14.1 C1_23_15.1 D1_22.2 D1_22_1.2 D1_22_2.2 D1_22_3.2 D1_22_4.2 D1_22_5.2 D1_22_6.2 D1_22_7.2 D1_22_8.2 D1_22_9.2 D1_22_10.2 D1_22_11.2 D1_22_12.2 D1_22_13.2 D1_22_14.2 D1_22_15.2 D1_23.2 D1_23_1.2 D1_23_2.2 D1_23_3.2 D1_23_4.2 D1_23_5.2 D1_23_6.2 D1_23_7.2 D1_23_8.2 D1_23_9.2 D1_23_10.2 D1_23_11.2 D1_23_12.2 D1_23_13.2 D1_23_14.2 D1_23_15.2 R1_22.2 R1_22_1.2 R1_22_2.2 R1_22_3.2 R1_22_4.2 R1_22_5.2 R1_22_6.2 R1_22_7.2 R1_22_8.2 R1_22_9.2 R1_22_10.2 R1_22_11.2 R1_22_12.2 R1_22_13.2 R1_22_14.2 R1_22_15.2 R1_23.2 R1_23_1.2 R1_23_2.2 R1_23_3.2 R1_23_4.2 R1_23_5.2 R1_23_6.2 R1_23_7.2 R1_23_8.2 R1_23_9.2 R1_23_10.2 R1_23_11.2 R1_23_12.2 R1_23_13.2 R1_23_14.2 R1_23_15.2 | length 7010.9
  Top Layer w10: D1_22.2@1274.5,1174 1260.5,1188 1260.5,1237.41 R1_22.2@1259.5,1238.41 1281.91,1238.41 1293.5,1250 1293.5,1342 ; C1_23.1@1438.09,1342 1469.5,1342 1469.5,1245 1462.91,1238.41 R1_23.2@1434.5,1238.41 1435.5,1237.41 1435.5,1188 D1_23.2@1449.5,1174 ; D1_22_1.2@1625.5,1174 1611.5,1188 1611.5,1237.41 R1_22_1.2@1610.5,1238.41 1632.91,1238.41 1644.5,1250 1644.5,1342 ; C1_23_1.1@1789.09,1342 1820.5,1342 1820.5,1245 1813.91,1238.41 R1_23_1.2@1785.5,1238.41 1786.5,1237.41 1786.5,1188 D1_23_1.2@1800.5,1174 ; D1_22_2.2@1975.5,1174 1961.5,1188 1961.5,1237.41 R1_22_2.2@1960.5,1238.41 1982.91,1238.41 1994.5,1250 1994.5,1342 ; C1_23_2.1@2139.09,1342 2170.5,1342 2170.5,1245 2163.91,1238.41 R1_23_2.2@2135.5,1238.41 2136.5,1237.41 2136.5,1188 D1_23_2.2@2150.5,1174 ; D1_22_3.2@2325.5,1174 2311.5,1188 2311.5,1237.41 R1_22_3.2@2310.5,1238.41 2332.91,1238.41 2344.5,1250 2344.5,1342 ; C1_23_3.1@2489.09,1342 2520.5,1342 2520.5,1245 2513.91,1238.41 R1_23_3.2@2485.5,1238.41 2486.5,1237.41 2486.5,1188 D1_23_3.2@2500.5,1174 ; D1_22_4.2@2675.5,1174 2661.5,1188 2661.5,1237.41 R1_22_4.2@2660.5,1238.41 2682.91,1238.41 2694.5,1250 2694.5,1342 ; C1_23_4.1@2839.09,1342 2870.5,1342 2870.5,1245 2863.91,1238.41 R1_23_4.2@2835.5,1238.41 2836.5,1237.41 2836.5,1188 D1_23_4.2@2850.5,1174 ; D1_22_5.2@3025.5,1174 3011.5,1188 3011.5,1237.41 R1_22_5.2@3010.5,1238.41 3032.91,1238.41 3044.5,1250 3044.5,1342 ; C1_23_5.1@3189.09,1342 3220.5,1342 3220.5,1245 3213.91,1238.41 R1_23_5.2@3185.5,1238.41 3186.5,1237.41 3186.5,1188 D1_23_5.2@3200.5,1174 ; D1_22_6.2@3375.5,1174 3361.5,1188 3361.5,1237.41 R1_22_6.2@3360.5,1238.41 3382.91,1238.41 3394.5,1250 3394.5,1342 ; C1_23_6.1@3539.09,1342 3570.5,1342 3570.5,1245 3563.91,1238.41 R1_23_6.2@3535.5,1238.41 3536.5,1237.41 3536.5,1188 D1_23_6.2@3550.5,1174 ; D1_22_7.2@3725.5,1174 3711.5,1188 3711.5,1237.41 R1_22_7.2@3710.5,1238.41 3732.91,1238.41 3744.5,1250 3744.5,1342 ; C1_23_7.1@3889.09,1342 3920.5,1342 3920.5,1245 3913.91,1238.41 R1_23_7.2@3885.5,1238.41 3886.5,1237.41 3886.5,1188 D1_23_7.2@3900.5,1174 ; D1_22_8.2@4075.5,1174 4061.5,1188 4061.5,1237.41 R1_22_8.2@4060.5,1238.41 4082.91,1238.41 4094.5,1250 4094.5,1342 ; C1_23_8.1@4239.09,1342 4270.5,1342 4270.5,1245 4263.91,1238.41 R1_23_8.2@4235.5,1238.41 4236.5,1237.41 4236.5,1188 D1_23_8.2@4250.5,1174 ; D1_22_9.2@4425.5,1174 4411.5,1188 4411.5,1237.41 R1_22_9.2@4410.5,1238.41 4432.91,1238.41 4444.5,1250 4444.5,1342 ; C1_23_9.1@4589.09,1342 4620.5,1342 4620.5,1245 4613.91,1238.41 R1_23_9.2@4585.5,1238.41 4586.5,1237.41 4586.5,1188 D1_23_9.2@4600.5,1174 ; D1_22_10.2@4775.5,1174 4761.5,1188 4761.5,1237.41 R1_22_10.2@4760.5,1238.41 4782.91,1238.41 4794.5,1250 4794.5,1342 ; C1_23_10.1@4939.09,1342 4970.5,1342 4970.5,1245 4963.91,1238.41 R1_23_10.2@4935.5,1238.41 4936.5,1237.41 4936.5,1188 D1_23_10.2@4950.5,1174 ; D1_22_11.2@5125.5,1174 5111.5,1188 5111.5,1237.41 R1_22_11.2@5110.5,1238.41 5132.91,1238.41 5144.5,1250 5144.5,1342 ; C1_23_11.1@5289.09,1342 5320.5,1342 5320.5,1245 5313.91,1238.41 R1_23_11.2@5285.5,1238.41 5286.5,1237.41 5286.5,1188 D1_23_11.2@5300.5,1174 ; D1_22_12.2@5475.5,1174 5461.5,1188 5461.5,1237.41 R1_22_12.2@5460.5,1238.41 5482.91,1238.41 5494.5,1250 5494.5,1342 ; C1_23_12.1@5639.09,1342 5670.5,1342 5670.5,1245 5663.91,1238.41 R1_23_12.2@5635.5,1238.41 5636.5,1237.41 5636.5,1188 D1_23_12.2@5650.5,1174 ; D1_22_13.2@5825.5,1174 5811.5,1188 5811.5,1237.41 R1_22_13.2@5810.5,1238.41 5832.91,1238.41 5844.5,1250 5844.5,1342 ; C1_23_13.1@5989.09,1342 6020.5,1342 6020.5,1245 6013.91,1238.41 R1_23_13.2@5985.5,1238.41 5986.5,1237.41 5986.5,1188 D1_23_13.2@6000.5,1174 ; D1_22_14.2@6175.5,1174 6161.5,1188 6161.5,1237.41 R1_22_14.2@6160.5,1238.41 6182.91,1238.41 6194.5,1250 6194.5,1342 ; C1_23_14.1@6339.09,1342 6370.5,1342 6370.5,1245 6363.91,1238.41 R1_23_14.2@6335.5,1238.41 6336.5,1237.41 6336.5,1188 D1_23_14.2@6350.5,1174 ; D1_22_15.2@6525.5,1174 6511.5,1188 6511.5,1237.41 R1_22_15.2@6510.5,1238.41 6532.91,1238.41 6544.5,1250 6544.5,1342 ; C1_23_15.1@6689.09,1342 6720.5,1342 6720.5,1245 6713.91,1238.41 R1_23_15.2@6685.5,1238.41 6686.5,1237.41 6686.5,1188 D1_23_15.2@6700.5,1174
NetC2_2: C2_22.2 C2_22_1.2 C2_22_2.2 C2_22_3.2 C2_22_4.2 C2_22_5.2 C2_22_6.2 C2_22_7.2 C2_22_8.2 C2_22_9.2 C2_22_10.2 C2_22_11.2 C2_22_12.2 C2_22_13.2 C2_22_14.2 C2_22_15.2 C2_23.2 C2_23_1.2 C2_23_2.2 C2_23_3.2 C2_23_4.2 C2_23_5.2 C2_23_6.2 C2_23_7.2 C2_23_8.2 C2_23_9.2 C2_23_10.2 C2_23_11.2 C2_23_12.2 C2_23_13.2 C2_23_14.2 C2_23_15.2 R2_22.1 R2_22_1.1 R2_22_2.1 R2_22_3.1 R2_22_4.1 R2_22_5.1 R2_22_6.1 R2_22_7.1 R2_22_8.1 R2_22_9.1 R2_22_10.1 R2_22_11.1 R2_22_12.1 R2_22_13.1 R2_22_14.1 R2_22_15.1 R2_23.1 R2_23_1.1 R2_23_2.1 R2_23_3.1 R2_23_4.1 R2_23_5.1 R2_23_6.1 R2_23_7.1 R2_23_8.1 R2_23_9.1 R2_23_10.1 R2_23_11.1 R2_23_12.1 R2_23_13.1 R2_23_14.1 R2_23_15.1 R3_22.2 R3_22_1.2 R3_22_2.2 R3_22_3.2 R3_22_4.2 R3_22_5.2 R3_22_6.2 R3_22_7.2 R3_22_8.2 R3_22_9.2 R3_22_10.2 R3_22_11.2 R3_22_12.2 R3_22_13.2 R3_22_14.2 R3_22_15.2 R3_23.2 R3_23_1.2 R3_23_2.2 R3_23_3.2 R3_23_4.2 R3_23_5.2 R3_23_6.2 R3_23_7.2 R3_23_8.2 R3_23_9.2 R3_23_10.2 R3_23_11.2 R3_23_12.2 R3_23_13.2 R3_23_14.2 R3_23_15.2 | length 4253.3
  Top Layer w10: R3_22.2@1233.91,1750 1233.91,1798.82 1265.09,1830 R2_22.1@1265.09,1870 ; R3_23.2@1408.91,1750 1408.91,1798.82 1440.09,1830 R2_23.1@1440.09,1870 ; R3_22_1.2@1584.91,1750 1584.91,1798.82 1616.09,1830 R2_22_1.1@1616.09,1870 ; R3_23_1.2@1759.91,1750 1759.91,1798.82 1791.09,1830 R2_23_1.1@1791.09,1870 ; R3_22_2.2@1934.91,1750 1934.91,1798.82 1966.09,1830 R2_22_2.1@1966.09,1870 ; R3_23_2.2@2109.91,1750 2109.91,1798.82 2141.09,1830 R2_23_2.1@2141.09,1870 ; R3_22_3.2@2284.91,1750 2284.91,1798.82 2316.09,1830 R2_22_3.1@2316.09,1870 ; R3_23_3.2@2459.91,1750 2459.91,1798.82 2491.09,1830 R2_23_3.1@2491.09,1870 ; R3_22_4.2@2634.91,1750 2634.91,1798.82 2666.09,1830 R2_22_4.1@2666.09,1870 ; R3_23_4.2@2809.91,1750 2809.91,1798.82 2841.09,1830 R2_23_4.1@2841.09,1870 ; R3_22_5.2@2984.91,1750 2984.91,1798.82 3016.09,1830 R2_22_5.1@3016.09,1870 ; R3_23_5.2@3159.91,1750 3159.91,1798.82 3191.09,1830 R2_23_5.1@3191.09,1870 ; R3_22_6.2@3334.91,1750 3334.91,1798.82 3366.09,1830 R2_22_6.1@3366.09,1870 ; R3_23_6.2@3509.91,1750 3509.91,1798.82 3541.09,1830 R2_23_6.1@3541.09,1870 ; R3_22_7.2@3684.91,1750 3684.91,1798.82 3716.09,1830 R2_22_7.1@3716.09,1870 ; R3_23_7.2@3859.91,1750 3859.91,1798.82 3891.09,1830 R2_23_7.1@3891.09,1870 ; R3_22_8.2@4034.91,1750 4034.91,1798.82 4066.09,1830 R2_22_8.1@4066.09,1870 ; R3_23_8.2@4209.91,1750 4209.91,1798.82 4241.09,1830 R2_23_8.1@4241.09,1870 ; R3_22_9.2@4384.91,1750 4384.91,1798.82 4416.09,1830 R2_22_9.1@4416.09,1870 ; R3_23_9.2@4559.91,1750 4559.91,1798.82 4591.09,1830 R2_23_9.1@4591.09,1870 ; R3_22_10.2@4734.91,1750 4734.91,1798.82 4766.09,1830 R2_22_10.1@4766.09,1870 ; R3_23_10.2@4909.91,1750 4909.91,1798.82 4941.09,1830 R2_23_10.1@4941.09,1870 ; R3_22_11.2@5084.91,1750 5084.91,1798.82 5116.09,1830 R2_22_11.1@5116.09,1870 ; R3_23_11.2@5259.91,1750 5259.91,1798.82 5291.09,1830 R2_23_11.1@5291.09,1870 ; R3_22_12.2@5434.91,1750 5434.91,1798.82 5466.09,1830 R2_22_12.1@5466.09,1870 ; R3_23_12.2@5609.91,1750 5609.91,1798.82 5641.09,1830 R2_23_12.1@5641.09,1870 ; R3_22_13.2@5784.91,1750 5784.91,1798.82 5816.09,1830 R2_22_13.1@5816.09,1870 ; R3_23_13.2@5959.91,1750 5959.91,1798.82 5991.09,1830 R2_23_13.1@5991.09,1870 ; R3_22_14.2@6134.91,1750 6134.91,1798.82 6166.09,1830 R2_22_14.1@6166.09,1870 ; R3_23_14.2@6309.91,1750 6309.91,1798.82 6341.09,1830 R2_23_14.1@6341.09,1870 ; R3_22_15.2@6484.91,1750 6484.91,1798.82 6516.09,1830 R2_22_15.1@6516.09,1870 ; R3_23_15.2@6659.91,1750 6659.91,1798.82 6691.09,1830 R2_23_15.1@6691.09,1870
NetC3_1: C3_22.1 C3_22_1.1 C3_22_2.1 C3_22_3.1 C3_22_4.1 C3_22_5.1 C3_22_6.1 C3_22_7.1 C3_22_8.1 C3_22_9.1 C3_22_10.1 C3_22_11.1 C3_22_12.1 C3_22_13.1 C3_22_14.1 C3_22_15.1 C3_23.1 C3_23_1.1 C3_23_2.1 C3_23_3.1 C3_23_4.1 C3_23_5.1 C3_23_6.1 C3_23_7.1 C3_23_8.1 C3_23_9.1 C3_23_10.1 C3_23_11.1 C3_23_12.1 C3_23_13.1 C3_23_14.1 C3_23_15.1 D1_22.1 D1_22_1.1 D1_22_2.1 D1_22_3.1 D1_22_4.1 D1_22_5.1 D1_22_6.1 D1_22_7.1 D1_22_8.1 D1_22_9.1 D1_22_10.1 D1_22_11.1 D1_22_12.1 D1_22_13.1 D1_22_14.1 D1_22_15.1 D1_23.1 D1_23_1.1 D1_23_2.1 D1_23_3.1 D1_23_4.1 D1_23_5.1 D1_23_6.1 D1_23_7.1 D1_23_8.1 D1_23_9.1 D1_23_10.1 D1_23_11.1 D1_23_12.1 D1_23_13.1 D1_23_14.1 D1_23_15.1 R6_22.2 R6_22_1.2 R6_22_2.2 R6_22_3.2 R6_22_4.2 R6_22_5.2 R6_22_6.2 R6_22_7.2 R6_22_8.2 R6_22_9.2 R6_22_10.2 R6_22_11.2 R6_22_12.2 R6_22_13.2 R6_22_14.2 R6_22_15.2 R6_23.2 R6_23_1.2 R6_23_2.2 R6_23_3.2 R6_23_4.2 R6_23_5.2 R6_23_6.2 R6_23_7.2 R6_23_8.2 R6_23_9.2 R6_23_10.2 R6_23_11.2 R6_23_12.2 R6_23_13.2 R6_23_14.2 R6_23_15.2 | length 9071.8
  Top Layer w10: D1_22.1@1174.5,1174 1167.5,1181 1167.5,1376 1173.91,1382.41 1173.91,1419 C3_22.1@1193.91,1439 ; D1_23.1@1343.5,1180 D1_23.1@1349.5,1174 1349.5,1216 1341.5,1224 1341.5,1411.59 C3_23.1@1368.91,1439 ; D1_22_1.1@1525.5,1174 1518.5,1181 1518.5,1376 1524.91,1382.41 1524.91,1419 C3_22_1.1@1544.91,1439 ; D1_23_1.1@1694.5,1180 D1_23_1.1@1700.5,1174 1700.5,1216 1692.5,1224 1692.5,1411.59 C3_23_1.1@1719.91,1439 ; D1_22_2.1@1875.5,1174 1868.5,1181 1868.5,1376 1874.91,1382.41 1874.91,1419 C3_22_2.1@1894.91,1439 ; D1_23_2.1@2044.5,1180 D1_23_2.1@2050.5,1174 2050.5,1216 2042.5,1224 2042.5,1411.59 C3_23_2.1@2069.91,1439 ; D1_22_3.1@2225.5,1174 2218.5,1181 2218.5,1376 2224.91,1382.41 2224.91,1419 C3_22_3.1@2244.91,1439 ; D1_23_3.1@2394.5,1180 D1_23_3.1@2400.5,1174 2400.5,1216 2392.5,1224 2392.5,1411.59 C3_23_3.1@2419.91,1439 ; D1_22_4.1@2575.5,1174 2568.5,1181 2568.5,1376 2574.91,1382.41 2574.91,1419 C3_22_4.1@2594.91,1439 ; D1_23_4.1@2744.5,1180 D1_23_4.1@2750.5,1174 2750.5,1216 2742.5,1224 2742.5,1411.59 C3_23_4.1@2769.91,1439 ; D1_22_5.1@2925.5,1174 2918.5,1181 2918.5,1376 2924.91,1382.41 2924.91,1419 C3_22_5.1@2944.91,1439 ; D1_23_5.1@3094.5,1180 D1_23_5.1@3100.5,1174 3100.5,1216 3092.5,1224 3092.5,1411.59 C3_23_5.1@3119.91,1439 ; D1_22_6.1@3275.5,1174 3268.5,1181 3268.5,1376 3274.91,1382.41 3274.91,1419 C3_22_6.1@3294.91,1439 ; D1_23_6.1@3444.5,1180 D1_23_6.1@3450.5,1174 3450.5,1216 3442.5,1224 3442.5,1411.59 C3_23_6.1@3469.91,1439 ; D1_22_7.1@3625.5,1174 3618.5,1181 3618.5,1376 3624.91,1382.41 3624.91,1419 C3_22_7.1@3644.91,1439 ; D1_23_7.1@3794.5,1180 D1_23_7.1@3800.5,1174 3800.5,1216 3792.5,1224 3792.5,1411.59 C3_23_7.1@3819.91,1439 ; D1_22_8.1@3975.5,1174 3968.5,1181 3968.5,1376 3974.91,1382.41 3974.91,1419 C3_22_8.1@3994.91,1439 ; D1_23_8.1@4144.5,1180 D1_23_8.1@4150.5,1174 4150.5,1216 4142.5,1224 4142.5,1411.59 C3_23_8.1@4169.91,1439 ; D1_22_9.1@4325.5,1174 4318.5,1181 4318.5,1376 4324.91,1382.41 4324.91,1419 C3_22_9.1@4344.91,1439 ; D1_23_9.1@4494.5,1180 D1_23_9.1@4500.5,1174 4500.5,1216 4492.5,1224 4492.5,1411.59 C3_23_9.1@4519.91,1439 ; D1_22_10.1@4675.5,1174 4668.5,1181 4668.5,1376 4674.91,1382.41 4674.91,1419 C3_22_10.1@4694.91,1439 ; D1_23_10.1@4844.5,1180 D1_23_10.1@4850.5,1174 4850.5,1216 4842.5,1224 4842.5,1411.59 C3_23_10.1@4869.91,1439 ; D1_22_11.1@5025.5,1174 5018.5,1181 5018.5,1376 5024.91,1382.41 5024.91,1419 C3_22_11.1@5044.91,1439 ; D1_23_11.1@5194.5,1180 D1_23_11.1@5200.5,1174 5200.5,1216 5192.5,1224 5192.5,1411.59 C3_23_11.1@5219.91,1439 ; D1_22_12.1@5375.5,1174 5368.5,1181 5368.5,1376 5374.91,1382.41 5374.91,1419 C3_22_12.1@5394.91,1439 ; D1_23_12.1@5544.5,1180 D1_23_12.1@5550.5,1174 5550.5,1216 5542.5,1224 5542.5,1411.59 C3_23_12.1@5569.91,1439 ; D1_22_13.1@5725.5,1174 5718.5,1181 5718.5,1376 5724.91,1382.41 5724.91,1419 C3_22_13.1@5744.91,1439 ; D1_23_13.1@5894.5,1180 D1_23_13.1@5900.5,1174 5900.5,1216 5892.5,1224 5892.5,1411.59 C3_23_13.1@5919.91,1439 ; D1_22_14.1@6075.5,1174 6068.5,1181 6068.5,1376 6074.91,1382.41 6074.91,1419 C3_22_14.1@6094.91,1439 ; D1_23_14.1@6244.5,1180 D1_23_14.1@6250.5,1174 6250.5,1216 6242.5,1224 6242.5,1411.59 C3_23_14.1@6269.91,1439 ; D1_22_15.1@6425.5,1174 6418.5,1181 6418.5,1376 6424.91,1382.41 6424.91,1419 C3_22_15.1@6444.91,1439 ; D1_23_15.1@6594.5,1180 D1_23_15.1@6600.5,1174 6600.5,1216 6592.5,1224 6592.5,1411.59 C3_23_15.1@6619.91,1439
NetC3_2: C3_22.2 C3_22_1.2 C3_22_2.2 C3_22_3.2 C3_22_4.2 C3_22_5.2 C3_22_6.2 C3_22_7.2 C3_22_8.2 C3_22_9.2 C3_22_10.2 C3_22_11.2 C3_22_12.2 C3_22_13.2 C3_22_14.2 C3_22_15.2 C3_23.2 C3_23_1.2 C3_23_2.2 C3_23_3.2 C3_23_4.2 C3_23_5.2 C3_23_6.2 C3_23_7.2 C3_23_8.2 C3_23_9.2 C3_23_10.2 C3_23_11.2 C3_23_12.2 C3_23_13.2 C3_23_14.2 C3_23_15.2 Q1_22.1 Q1_22_1.1 Q1_22_2.1 Q1_22_3.1 Q1_22_4.1 Q1_22_5.1 Q1_22_6.1 Q1_22_7.1 Q1_22_8.1 Q1_22_9.1 Q1_22_10.1 Q1_22_11.1 Q1_22_12.1 Q1_22_13.1 Q1_22_14.1 Q1_22_15.1 Q1_23.1 Q1_23_1.1 Q1_23_2.1 Q1_23_3.1 Q1_23_4.1 Q1_23_5.1 Q1_23_6.1 Q1_23_7.1 Q1_23_8.1 Q1_23_9.1 Q1_23_10.1 Q1_23_11.1 Q1_23_12.1 Q1_23_13.1 Q1_23_14.1 Q1_23_15.1 R5_22.1 R5_22_1.1 R5_22_2.1 R5_22_3.1 R5_22_4.1 R5_22_5.1 R5_22_6.1 R5_22_7.1 R5_22_8.1 R5_22_9.1 R5_22_10.1 R5_22_11.1 R5_22_12.1 R5_22_13.1 R5_22_14.1 R5_22_15.1 R5_23.1 R5_23_1.1 R5_23_2.1 R5_23_3.1 R5_23_4.1 R5_23_5.1 R5_23_6.1 R5_23_7.1 R5_23_8.1 R5_23_9.1 R5_23_10.1 R5_23_11.1 R5_23_12.1 R5_23_13.1 R5_23_14.1 R5_23_15.1 R8_22.2 R8_22_1.2 R8_22_2.2 R8_22_3.2 R8_22_4.2 R8_22_5.2 R8_22_6.2 R8_22_7.2 R8_22_8.2 R8_22_9.2 R8_22_10.2 R8_22_11.2 R8_22_12.2 R8_22_13.2 R8_22_14.2 R8_22_15.2 R8_23.2 R8_23_1.2 R8_23_2.2 R8_23_3.2 R8_23_4.2 R8_23_5.2 R8_23_6.2 R8_23_7.2 R8_23_8.2 R8_23_9.2 R8_23_10.2 R8_23_11.2 R8_23_12.2 R8_23_13.2 R8_23_14.2 R8_23_15.2 | length 9729.5
  Top Layer w10: C3_22.2@1245.09,1449 C3_22.2@1245.09,1439 1271.5,1439 1285.09,1452.59 R8_22.2@1285.09,1489 ; Q1_22.1@1265.09,1635.15 R5_22.1@1265.09,1697 ; Q1_22.1@1265.9,1631.34 1265.9,1542.6 1285,1523.5 R8_22.2@1285,1489.09 ; C3_23.2@1420.09,1449 C3_23.2@1420.09,1439 1446.5,1439 1460.09,1452.59 R8_23.2@1460.09,1489 ; Q1_23.1@1440.09,1635.15 R5_23.1@1440.09,1697 ; Q1_23.1@1440.9,1631.34 1440.9,1542.6 1460,1523.5 R8_23.2@1460,1489.09 ; C3_22_1.2@1596.09,1449 C3_22_1.2@1596.09,1439 1622.5,1439 1636.09,1452.59 R8_22_1.2@1636.09,1489 ; Q1_22_1.1@1616.09,1635.15 R5_22_1.1@1616.09,1697 ; Q1_22_1.1@1616.9,1631.34 1616.9,1542.6 1636,1523.5 R8_22_1.2@1636,1489.09 ; C3_23_1.2@1771.09,1449 C3_23_1.2@1771.09,1439 1797.5,1439 1811.09,1452.59 R8_23_1.2@1811.09,1489 ; Q1_23_1.1@1791.09,1635.15 R5_23_1.1@1791.09,1697 ; Q1_23_1.1@1791.9,1631.34 1791.9,1542.6 1811,1523.5 R8_23_1.2@1811,1489.09 ; C3_22_2.2@1946.09,1449 C3_22_2.2@1946.09,1439 1972.5,1439 1986.09,1452.59 R8_22_2.2@1986.09,1489 ; Q1_22_2.1@1966.09,1635.15 R5_22_2.1@1966.09,1697 ; Q1_22_2.1@1966.9,1631.34 1966.9,1542.6 1986,1523.5 R8_22_2.2@1986,1489.09 ; C3_23_2.2@2121.09,1449 C3_23_2.2@2121.09,1439 2147.5,1439 2161.09,1452.59 R8_23_2.2@2161.09,1489 ; Q1_23_2.1@2141.09,1635.15 R5_23_2.1@2141.09,1697 ; Q1_23_2.1@2141.9,1631.34 2141.9,1542.6 2161,1523.5 R8_23_2.2@2161,1489.09 ; C3_22_3.2@2296.09,1449 C3_22_3.2@2296.09,1439 2322.5,1439 2336.09,1452.59 R8_22_3.2@2336.09,1489 ; Q1_22_3.1@2316.09,1635.15 R5_22_3.1@2316.09,1697 ; Q1_22_3.1@2316.9,1631.34 2316.9,1542.6 2336,1523.5 R8_22_3.2@2336,1489.09 ; C3_23_3.2@2471.09,1449 C3_23_3.2@2471.09,1439 2497.5,1439 2511.09,1452.59 R8_23_3.2@2511.09,1489 ; Q1_23_3.1@2491.09,1635.15 R5_23_3.1@2491.09,1697 ; Q1_23_3.1@2491.9,1631.34 2491.9,1542.6 2511,1523.5 R8_23_3.2@2511,1489.09 ; C3_22_4.2@2646.09,1449 C3_22_4.2@2646.09,1439 2672.5,1439 2686.09,1452.59 R8_22_4.2@2686.09,1489 ; Q1_22_4.1@2666.09,1635.15 R5_22_4.1@2666.09,1697 ; Q1_22_4.1@2666.9,1631.34 2666.9,1542.6 2686,1523.5 R8_22_4.2@2686,1489.09 ; C3_23_4.2@2821.09,1449 C3_23_4.2@2821.09,1439 2847.5,1439 2861.09,1452.59 R8_23_4.2@2861.09,1489 ; Q1_23_4.1@2841.09,1635.15 R5_23_4.1@2841.09,1697 ; Q1_23_4.1@2841.9,1631.34 2841.9,1542.6 2861,1523.5 R8_23_4.2@2861,1489.09 ; C3_22_5.2@2996.09,1449 C3_22_5.2@2996.09,1439 3022.5,1439 3036.09,1452.59 R8_22_5.2@3036.09,1489 ; Q1_22_5.1@3016.09,1635.15 R5_22_5.1@3016.09,1697 ; Q1_22_5.1@3016.9,1631.34 3016.9,1542.6 3036,1523.5 R8_22_5.2@3036,1489.09 ; C3_23_5.2@3171.09,1449 C3_23_5.2@3171.09,1439 3197.5,1439 3211.09,1452.59 R8_23_5.2@3211.09,1489 ; Q1_23_5.1@3191.09,1635.15 R5_23_5.1@3191.09,1697 ; Q1_23_5.1@3191.9,1631.34 3191.9,1542.6 3211,1523.5 R8_23_5.2@3211,1489.09 ; C3_22_6.2@3346.09,1449 C3_22_6.2@3346.09,1439 3372.5,1439 3386.09,1452.59 R8_22_6.2@3386.09,1489 ; Q1_22_6.1@3366.09,1635.15 R5_22_6.1@3366.09,1697 ; Q1_22_6.1@3366.9,1631.34 3366.9,1542.6 3386,1523.5 R8_22_6.2@3386,1489.09 ; C3_23_6.2@3521.09,1449 C3_23_6.2@3521.09,1439 3547.5,1439 3561.09,1452.59 R8_23_6.2@3561.09,1489 ; Q1_23_6.1@3541.09,1635.15 R5_23_6.1@3541.09,1697 ; Q1_23_6.1@3541.9,1631.34 3541.9,1542.6 3561,1523.5 R8_23_6.2@3561,1489.09 ; C3_22_7.2@3696.09,1449 C3_22_7.2@3696.09,1439 3722.5,1439 3736.09,1452.59 R8_22_7.2@3736.09,1489 ; Q1_22_7.1@3716.09,1635.15 R5_22_7.1@3716.09,1697 ; Q1_22_7.1@3716.9,1631.34 3716.9,1542.6 3736,1523.5 R8_22_7.2@3736,1489.09 ; C3_23_7.2@3871.09,1449 C3_23_7.2@3871.09,1439 3897.5,1439 3911.09,1452.59 R8_23_7.2@3911.09,1489 ; Q1_23_7.1@3891.09,1635.15 R5_23_7.1@3891.09,1697 ; Q1_23_7.1@3891.9,1631.34 3891.9,1542.6 3911,1523.5 R8_23_7.2@3911,1489.09 ; C3_22_8.2@4046.09,1449 C3_22_8.2@4046.09,1439 4072.5,1439 4086.09,1452.59 R8_22_8.2@4086.09,1489 ; Q1_22_8.1@4066.09,1635.15 R5_22_8.1@4066.09,1697 ; Q1_22_8.1@4066.9,1631.34 4066.9,1542.6 4086,1523.5 R8_22_8.2@4086,1489.09 ; C3_23_8.2@4221.09,1449 C3_23_8.2@4221.09,1439 4247.5,1439 4261.09,1452.59 R8_23_8.2@4261.09,1489 ; Q1_23_8.1@4241.09,1635.15 R5_23_8.1@4241.09,1697 ; Q1_23_8.1@4241.9,1631.34 4241.9,1542.6 4261,1523.5 R8_23_8.2@4261,1489.09 ; C3_22_9.2@4396.09,1449 C3_22_9.2@4396.09,1439 4422.5,1439 4436.09,1452.59 R8_22_9.2@4436.09,1489 ; Q1_22_9.1@4416.09,1635.15 R5_22_9.1@4416.09,1697 ; Q1_22_9.1@4416.9,1631.34 4416.9,1542.6 4436,1523.5 R8_22_9.2@4436,1489.09 ; C3_23_9.2@4571.09,1449 C3_23_9.2@4571.09,1439 4597.5,1439 4611.09,1452.59 R8_23_9.2@4611.09,1489 ; Q1_23_9.1@4591.09,1635.15 R5_23_9.1@4591.09,1697 ; Q1_23_9.1@4591.9,1631.34 4591.9,1542.6 4611,1523.5 R8_23_9.2@4611,1489.09 ; C3_22_10.2@4746.09,1449 C3_22_10.2@4746.09,1439 4772.5,1439 4786.09,1452.59 R8_22_10.2@4786.09,1489 ; Q1_22_10.1@4766.09,1635.15 R5_22_10.1@4766.09,1697 ; Q1_22_10.1@4766.9,1631.34 4766.9,1542.6 4786,1523.5 R8_22_10.2@4786,1489.09 ; C3_23_10.2@4921.09,1449 C3_23_10.2@4921.09,1439 4947.5,1439 4961.09,1452.59 R8_23_10.2@4961.09,1489 ; Q1_23_10.1@4941.09,1635.15 R5_23_10.1@4941.09,1697 ; Q1_23_10.1@4941.9,1631.34 4941.9,1542.6 4961,1523.5 R8_23_10.2@4961,1489.09 ; C3_22_11.2@5096.09,1449 C3_22_11.2@5096.09,1439 5122.5,1439 5136.09,1452.59 R8_22_11.2@5136.09,1489 ; Q1_22_11.1@5116.09,1635.15 R5_22_11.1@5116.09,1697 ; Q1_22_11.1@5116.9,1631.34 5116.9,1542.6 5136,1523.5 R8_22_11.2@5136,1489.09 ; C3_23_11.2@5271.09,1449 C3_23_11.2@5271.09,1439 5297.5,1439 5311.09,1452.59 R8_23_11.2@5311.09,1489 ; Q1_23_11.1@5291.09,1635.15 R5_23_11.1@5291.09,1697 ; Q1_23_11.1@5291.9,1631.34 5291.9,1542.6 5311,1523.5 R8_23_11.2@5311,1489.09 ; C3_22_12.2@5446.09,1449 C3_22_12.2@5446.09,1439 5472.5,1439 5486.09,1452.59 R8_22_12.2@5486.09,1489 ; Q1_22_12.1@5466.09,1635.15 R5_22_12.1@5466.09,1697 ; Q1_22_12.1@5466.9,1631.34 5466.9,1542.6 5486,1523.5 R8_22_12.2@5486,1489.09 ; C3_23_12.2@5621.09,1449 C3_23_12.2@5621.09,1439 5647.5,1439 5661.09,1452.59 R8_23_12.2@5661.09,1489 ; Q1_23_12.1@5641.09,1635.15 R5_23_12.1@5641.09,1697 ; Q1_23_12.1@5641.9,1631.34 5641.9,1542.6 5661,1523.5 R8_23_12.2@5661,1489.09 ; C3_22_13.2@5796.09,1449 C3_22_13.2@5796.09,1439 5822.5,1439 5836.09,1452.59 R8_22_13.2@5836.09,1489 ; Q1_22_13.1@5816.09,1635.15 R5_22_13.1@5816.09,1697 ; Q1_22_13.1@5816.9,1631.34 5816.9,1542.6 5836,1523.5 R8_22_13.2@5836,1489.09 ; C3_23_13.2@5971.09,1449 C3_23_13.2@5971.09,1439 5997.5,1439 6011.09,1452.59 R8_23_13.2@6011.09,1489 ; Q1_23_13.1@5991.09,1635.15 R5_23_13.1@5991.09,1697 ; Q1_23_13.1@5991.9,1631.34 5991.9,1542.6 6011,1523.5 R8_23_13.2@6011,1489.09 ; C3_22_14.2@6146.09,1449 C3_22_14.2@6146.09,1439 6172.5,1439 6186.09,1452.59 R8_22_14.2@6186.09,1489 ; Q1_22_14.1@6166.09,1635.15 R5_22_14.1@6166.09,1697 ; Q1_22_14.1@6166.9,1631.34 6166.9,1542.6 6186,1523.5 R8_22_14.2@6186,1489.09 ; C3_23_14.2@6321.09,1449 C3_23_14.2@6321.09,1439 6347.5,1439 6361.09,1452.59 R8_23_14.2@6361.09,1489 ; Q1_23_14.1@6341.09,1635.15 R5_23_14.1@6341.09,1697 ; Q1_23_14.1@6341.9,1631.34 6341.9,1542.6 6361,1523.5 R8_23_14.2@6361,1489.09 ; C3_22_15.2@6496.09,1449 C3_22_15.2@6496.09,1439 6522.5,1439 6536.09,1452.59 R8_22_15.2@6536.09,1489 ; Q1_22_15.1@6516.09,1635.15 R5_22_15.1@6516.09,1697 ; Q1_22_15.1@6516.9,1631.34 6516.9,1542.6 6536,1523.5 R8_22_15.2@6536,1489.09 ; C3_23_15.2@6671.09,1449 C3_23_15.2@6671.09,1439 6697.5,1439 6711.09,1452.59 R8_23_15.2@6711.09,1489 ; Q1_23_15.1@6691.09,1635.15 R5_23_15.1@6691.09,1697 ; Q1_23_15.1@6691.9,1631.34 6691.9,1542.6 6711,1523.5 R8_23_15.2@6711,1489.09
